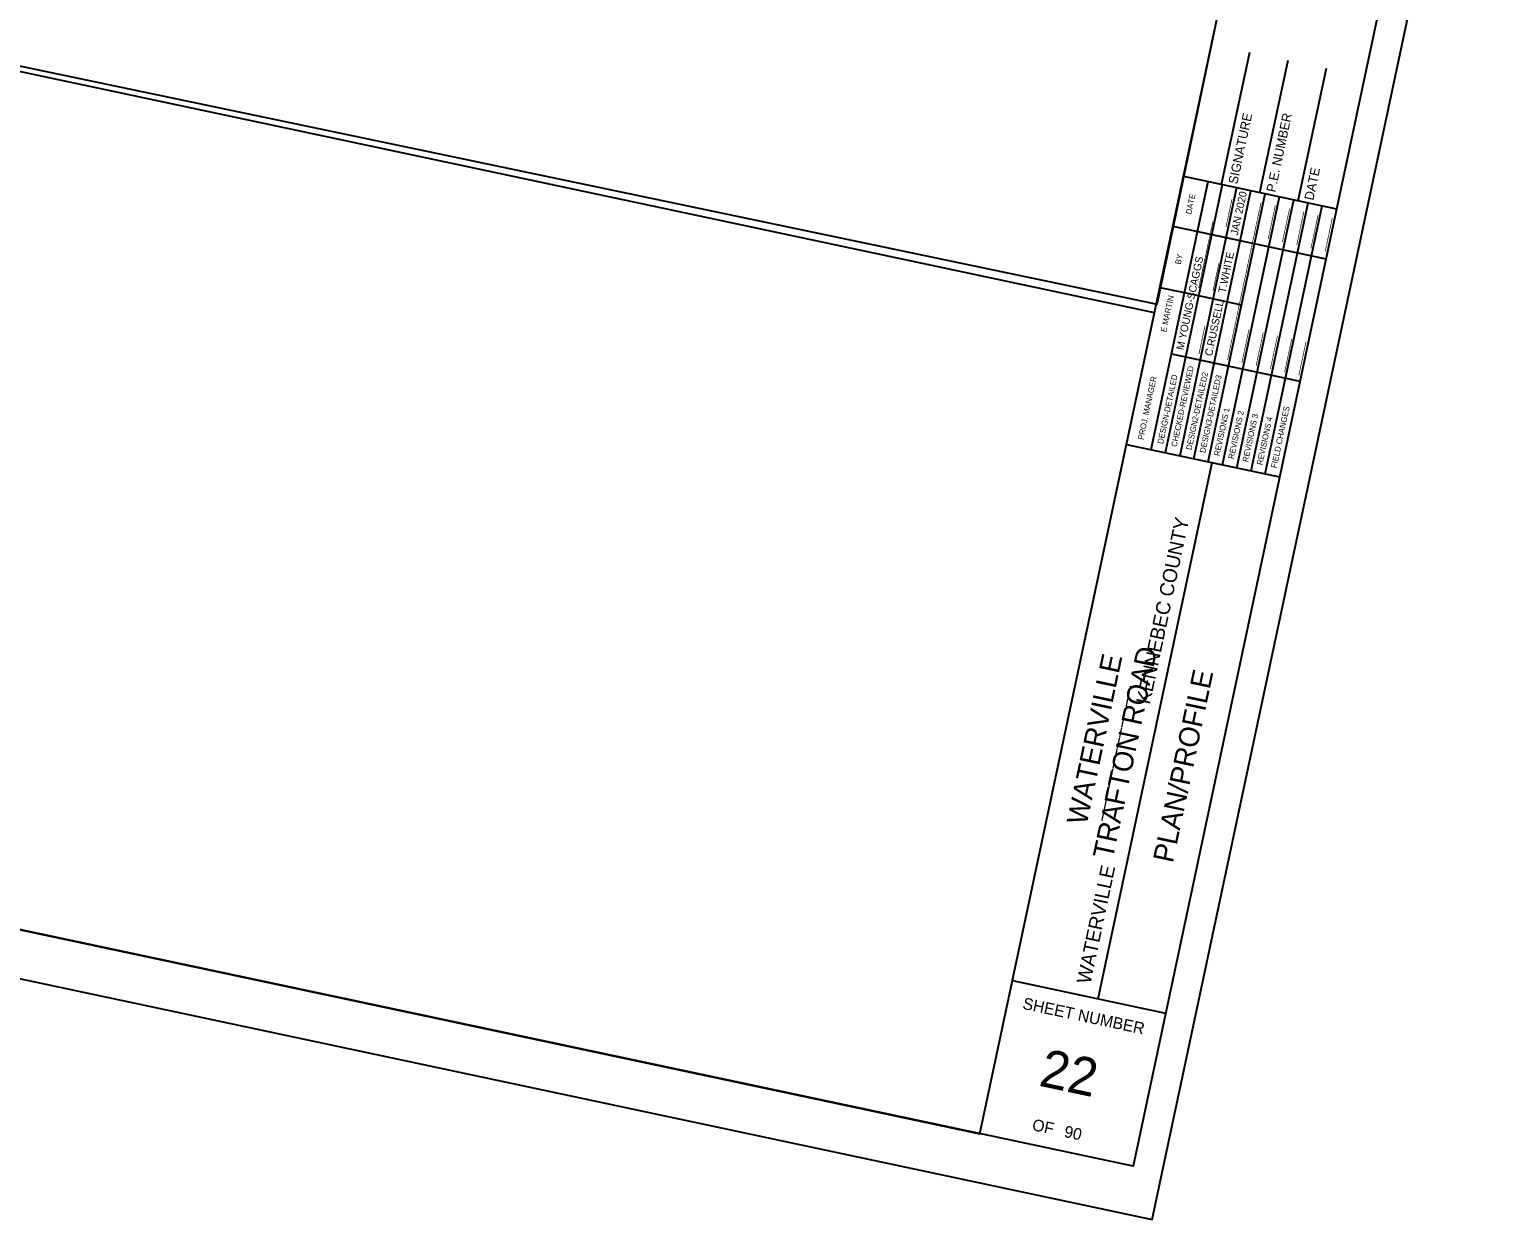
# Model space of a CAD drawing. Extents: x 1161043 to 1161989, y 610342 to 611057.
# Drawn here: x 1161516.3 to 1161989.2, y 610342.3 to 610722.2 of the extents above; entities that cross this region are included whole.
import ezdxf

# ---------------------------------------------------------------- set-up
doc = ezdxf.new("R2010")
doc.units = 0
for name, color, linetype in [('BORDER', 7, 'Continuous'), ('BRIDGE_TITLE', 7, 'Continuous'), ('CLIPS', 7, 'Continuous'), ('HIGHWAY_TITLE', 7, 'Continuous'), ('PLOT BOUNDARY', 7, 'Continuous')]:
    doc.layers.add(name, color=color, linetype=linetype)

msp = doc.modelspace()

# ---------------------------------------------------------------- linework, layer by layer
at = {"layer": 'BORDER'}
for p, q in [((1161819.77, 610369.67), (1161928.93, 610883.2)), ((1161896.97, 610672.76), (1161905.96, 610715.05)), ((1161909.2, 610670.16), (1161918.19, 610712.45)), ((1161921.43, 610667.56), (1161930.42, 610709.86)), ((1161884.75, 610675.36), (1161933.66, 610664.96)), ((1161866.56, 610589.77), (1161915.46, 610579.38)), ((1161857.52, 610412.78), (1161893.9, 610583.96)), ((1161830.17, 610418.6), (1161879.08, 610408.2))]:
    msp.add_line(p, q, dxfattribs=at)
msp.add_lwpolyline([(1161195.32, 611039.14), (1161977.83, 610872.81), (1161868.68, 610359.28), (1161086.16, 610525.61)], close=True, dxfattribs=at)
for points in [[(1161874.46, 610588.11), (1161891.92, 610670.23)], [(1161879.02, 610587.14), (1161897.21, 610672.71)], [(1161901.76, 610671.74), (1161883.57, 610586.17)], [(1161888.13, 610585.2), (1161906.32, 610670.77)], [(1161889.27, 610657.79), (1161892.65, 610673.68)], [(1161892.69, 610584.23), (1161910.88, 610669.81)], [(1161897.24, 610583.26), (1161915.43, 610668.84)], [(1161901.8, 610582.3), (1161919.99, 610667.87)], [(1161906.36, 610581.33), (1161924.55, 610666.9)], [(1161910.91, 610580.36), (1161929.1, 610665.93)], [(1161881.37, 610659.46), (1161930.28, 610649.07)], [(1161877.21, 610639.9), (1161885.11, 610638.22)], [(1161885.11, 610638.22), (1161903.34, 610634.35)], [(1161880.95, 610618.66), (1161921.96, 610609.94)]]:
    msp.add_lwpolyline(points, dxfattribs=at)
at = {"layer": 'CLIPS'}
for points in [[(1161142.37, 610788.34), (1161876.39, 610634.52), (1161927.67, 610879.21), (1161193.65, 611033.03)], [(1161086.16, 610525.61), (1161819.77, 610369.67), (1161875.49, 610631.82), (1161141.88, 610787.75)]]:
    msp.add_lwpolyline(points, close=True, dxfattribs=at)
at = {"layer": 'PLOT BOUNDARY'}
msp.add_lwpolyline([(1161043.4, 610519.06), (1161874.82, 610342.33), (1161989.18, 610880.32), (1161157.75, 611057.04)], close=True, dxfattribs=at)

# ---------------------------------------------------------------- texts
at = {"layer": 'BORDER'}
for s, height, rotation, p in [('SIGNATURE', 2.953, 78, (1161901.97, 610672.68)), ('P.E. NUMBER', 2.9528, 78, (1161914.1, 610670.1)), ('DATE', 2.953, 78, (1161926.23, 610667.52)), ('DATE', 1.857, 78, (1161887.27, 610663.09)), ('JAN 2020', 2.423, 78, (1161902.11, 610656.36)), ('_____', 2.423, 78, (1161897.79, 610659.32)), ('______', 2.423, 78, (1161906.71, 610656.51)), ('______', 2.423, 78, (1161911.27, 610655.55)), ('______', 2.423, 78, (1161915.83, 610654.59)), ('____________', 2.4227, 78, (1161889.08, 610639.86)), ('______', 2.423, 78, (1161920.39, 610653.62)), ('______', 2.423, 78, (1161924.91, 610652.5)), ('______', 2.423, 78, (1161929.47, 610651.53)), ('____________', 2.4227, 78, (1161902.56, 610636.99)), ('BY', 1.857, 78, (1161883.87, 610647.1)), ('T.WHITE', 2.423, 78, (1161898.19, 610637.92)), ('M YOUNG-SCAGGS', 2.4227, 78, (1161884.8, 610619.75)), ('_____', 2.423, 78, (1161893.63, 610638.89)), ('E MARTIN', 1.864, 78, (1161879.28, 610625.49)), ('____________', 2.4227, 78, (1161898.29, 610616.88)), ('C.RUSSELL', 2.423, 78, (1161893.91, 610617.81)), ('_____', 2.423, 78, (1161889.18, 610618.82)), ('______', 2.423, 78, (1161902.85, 610615.91)), ('______', 2.423, 78, (1161907.4, 610614.95)), ('______', 2.423, 78, (1161911.96, 610613.98)), ('______', 2.423, 78, (1161916.52, 610613.01)), ('______', 2.423, 78, (1161921.07, 610612.04)), ('CHECKED-REVIEWED', 1.8637, 78, (1161882.62, 610588.85)), ('DESIGN2-DETAILED2', 1.8637, 78, (1161887.36, 610587.84)), ('PROJ. MANAGER', 1.8637, 78, (1161871.97, 610591.11)), ('DESIGN-DETAILED', 1.8637, 78, (1161878.25, 610589.78)), ('DESIGN3-DETAILED3', 1.8637, 78, (1161891.73, 610586.91)), ('REVISIONS 1', 1.8637, 78, (1161896.29, 610585.95)), ('REVISIONS 2', 1.8637, 78, (1161900.85, 610584.98)), ('REVISIONS 3', 1.8637, 78, (1161905.4, 610584.01)), ('REVISIONS 4', 1.8637, 78, (1161909.96, 610583.04)), ('FIELD CHANGES', 1.8637, 78, (1161914.52, 610582.07)), ('PLAN/PROFILE', 6.5214, 78, (1161881.37, 610455.89)), ('SHEET NUMBER', 3.7264, 348, (1161833.19, 610409.59)), ('22', 12.097, 348, (1161838.26, 610385.08)), ('OF', 3.726, 348, (1161836.21, 610370.85)), ('90', 3.726, 348, (1161846.43, 610368.67))]:
    msp.add_text(s, height=height, rotation=rotation, dxfattribs=at).set_placement(p)
at = {"layer": 'BRIDGE_TITLE'}
for s, height, p in [('KENNEBEC COUNTY', 4.5358, (1161874.02, 610506.55)), ('_____________', 4.5358, (1161857.66, 610469.94)), ('WATERVILLE', 4.536, (1161855.04, 610417.26))]:
    msp.add_text(s, height=height, rotation=78, dxfattribs=at).set_placement(p)
at = {"layer": 'HIGHWAY_TITLE'}
for s, height, p in [('WATERVILLE', 6.521, (1161853.82, 610467.97)), ('TRAFTON ROAD', 6.5214, (1161862.17, 610457.1))]:
    msp.add_text(s, height=height, rotation=78, dxfattribs=at).set_placement(p)

doc.saveas('drawing.dxf')
